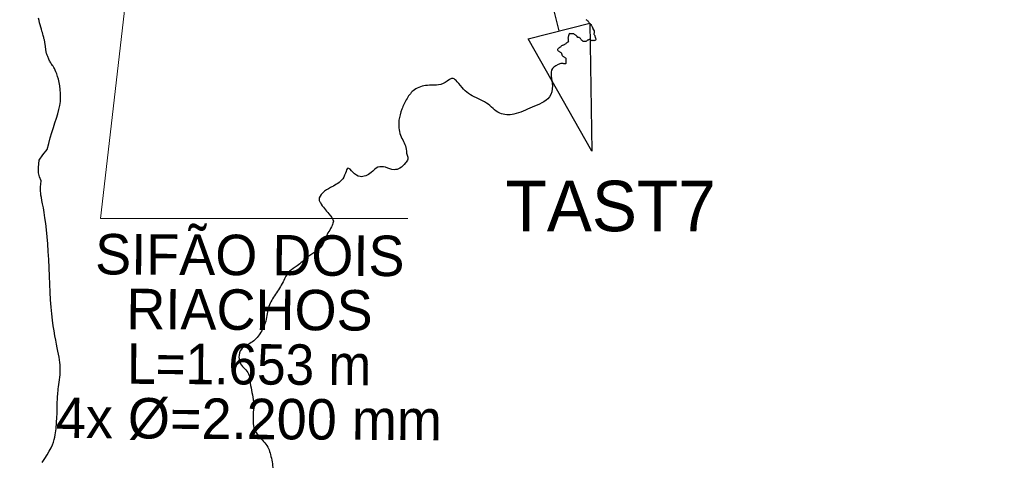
# Model space of a CAD drawing. Extents: x -1643653 to 4543381, y 1624270 to 13878484.
# Drawn here: x 707705 to 717468, y 8950266 to 8954621 of the extents above; entities that cross this region are included whole.
import ezdxf
from ezdxf.enums import TextEntityAlignment as Align

# ---------------------------------------------------------------- set-up
doc = ezdxf.new("R2010")
doc.units = 0
doc.header["$LTSCALE"] = 160
for name, color, linetype, lineweight in [('24', 7, 'Continuous', 25), ('50', 7, 'Continuous', 13), ('54', 7, 'Continuous', 25), ('60', 7, 'Continuous', 13)]:
    doc.layers.add(name, color=color, linetype=linetype, lineweight=lineweight)

msp = doc.modelspace()

# ---------------------------------------------------------------- linework, layer by layer
at = {"layer": '24'}
for points in [[(707956, 8954384.1), (707954.9, 8954391.2), (707953.6, 8954398.5), (707952.2, 8954405.9), (707950.7, 8954413.4), (707949.1, 8954421), (707947.3, 8954428.8), (707945.3, 8954437.1), (707943, 8954446), (707940.4, 8954455.9), (707937.4, 8954466.9), (707933.9, 8954479.4), (707929.9, 8954493.6), (707925.3, 8954509.7), (707920.2, 8954528), (707914.5, 8954548.1), (707908.6, 8954569.4), (707902.5, 8954591.7), (707896.6, 8954614.5), (707890.9, 8954637.2)], [(713307, 8954625.1), (713312.2, 8954621.1), (713317.1, 8954618.2), (713321.9, 8954614.9), (713325.6, 8954610), (713329.4, 8954605.2), (713333.2, 8954600.5), (713336.7, 8954595.9), (713341.3, 8954591.5), (713344.4, 8954587), (713349, 8954582.3), (713353.6, 8954578.9), (713358.5, 8954573.9), (713360.9, 8954569), (713363.1, 8954563.9), (713365.8, 8954556.9), (713369.7, 8954551.6), (713372.7, 8954547.2), (713374.2, 8954542.2), (713375.5, 8954537.1), (713376.9, 8954531.6), (713390.6, 8954512.4)], [(713229.2, 8954445.5), (713220.4, 8954455.7), (713214.5, 8954461.2), (713210.9, 8954465.8), (713206.4, 8954468.9), (713201.3, 8954471.5), (713195.4, 8954474.7), (713191.7, 8954478.3), (713187.4, 8954482.7), (713180.8, 8954482.6), (713175.8, 8954481.5), (713170.8, 8954480.4), (713165.2, 8954480.4), (713159.8, 8954482.2), (713154.6, 8954483), (713147.7, 8954483.7), (713141.9, 8954481.6), (713138.1, 8954470.5), (713137.2, 8954462.9), (713136.5, 8954457.3), (713133.9, 8954451.5), (713131.7, 8954446.4), (713130.2, 8954441), (713130.9, 8954436), (713131.5, 8954430.1), (713132.8, 8954422.3), (713133.5, 8954416.6), (713134.1, 8954410.6), (713133.8, 8954405.6), (713131.6, 8954401.1), (713127.6, 8954398), (713122.8, 8954395.4), (713118.2, 8954392.8), (713113.5, 8954388.2), (713109.7, 8954384.6), (713103.8, 8954381), (713097.1, 8954377.7), (713091.9, 8954374.4), (713085.8, 8954371.3), (713080.7, 8954368.8), (713074.7, 8954366.9), (713067.9, 8954362.2), (713063.7, 8954358.6), (713059.7, 8954355.1), (713055.1, 8954351.5), (713048.2, 8954347.9), (713042.8, 8954344.3), (713038.6, 8954340.4), (713035, 8954335.6), (713030.7, 8954331.8), (713028, 8954327.5), (713027.8, 8954322.3), (713029.7, 8954317.1), (713033.4, 8954312.2), (713038.7, 8954309.1), (713043.6, 8954307.2), (713048.9, 8954304.3), (713054.5, 8954301.2), (713059, 8954298), (713062.8, 8954294.3), (713065.3, 8954289.8), (713066.8, 8954284.8), (713069.4, 8954280.2), (713070.9, 8954274.6), (713073.7, 8954269.2)], [(713390.6, 8954512.4), (713390.3, 8954505.2), (713389.8, 8954499.3), (713389.5, 8954493.5), (713387.8, 8954479.9), (713389.8, 8954474.5), (713392.8, 8954469.2), (713395.3, 8954464.4), (713396.6, 8954457.8), (713398.5, 8954452.9), (713401.1, 8954447.1), (713402.7, 8954442.3), (713404.4, 8954437.5), (713405.7, 8954431.2), (713405.7, 8954426), (713404.1, 8954420.3), (713398.7, 8954415.7), (713392.6, 8954414.4), (713387, 8954414.2), (713381.8, 8954415.9), (713374.3, 8954414.9), (713367.8, 8954414.2), (713362.5, 8954416.7), (713357.9, 8954419.2), (713352.6, 8954422.4), (713345.1, 8954425), (713339.8, 8954424.3), (713335.1, 8954422.7), (713329, 8954420.7), (713324.1, 8954419.2), (713319.3, 8954416), (713313.1, 8954410.9), (713307.6, 8954407.2), (713300.2, 8954406.6), (713294, 8954405.8), (713288.1, 8954405.2), (713280.9, 8954407.3), (713276.2, 8954409.8), (713271, 8954414.4), (713265.9, 8954419.2), (713261.2, 8954424.5), (713258.1, 8954429), (713253.9, 8954434.3), (713250, 8954438.7), (713245.6, 8954442.5), (713240.2, 8954444.2), (713229.2, 8954445.5)], [(708079.3, 8954060.8), (708071.1, 8954085.7), (708063.2, 8954106.6), (708055.7, 8954124), (708048.6, 8954138.5), (708041.7, 8954150.6), (708035.2, 8954160.9), (708029.1, 8954169.9), (708023.1, 8954178.3), (708017.4, 8954186.5), (708012, 8954195), (708006.8, 8954203.9), (708001.8, 8954213), (707997.2, 8954222.1), (707992.8, 8954231.2), (707988.8, 8954240.2), (707985.1, 8954248.9), (707981.7, 8954257.1), (707978.7, 8954264.9), (707976, 8954272.2), (707973.6, 8954279.2), (707971.6, 8954285.9), (707969.7, 8954292.3), (707968.1, 8954298.6), (707966.8, 8954304.8), (707965.5, 8954311), (707964.5, 8954317.3), (707963.5, 8954323.6), (707962.7, 8954330.1), (707961.9, 8954336.5), (707961.2, 8954343.1), (707960.4, 8954349.7), (707959.7, 8954356.5), (707958.9, 8954363.2), (707958, 8954370.1), (707957.1, 8954377), (707956, 8954384.1)], [(708079.3, 8954060.8), (708071.1, 8954085.7), (708063.2, 8954106.6), (708055.7, 8954124), (708048.6, 8954138.5), (708041.7, 8954150.6), (708035.2, 8954160.9), (708029.1, 8954169.9), (708023.1, 8954178.3), (708017.4, 8954186.5), (708012, 8954195), (708006.8, 8954203.9), (708001.8, 8954213), (707997.2, 8954222.1), (707992.8, 8954231.2), (707988.8, 8954240.2), (707985.1, 8954248.9), (707981.7, 8954257.1), (707978.7, 8954264.9), (707976, 8954272.2), (707973.6, 8954279.2), (707971.6, 8954285.9), (707969.7, 8954292.3), (707968.1, 8954298.6), (707966.8, 8954304.8), (707965.5, 8954311), (707964.5, 8954317.3), (707963.5, 8954323.6), (707962.7, 8954330.1), (707961.9, 8954336.5), (707961.2, 8954343.1), (707960.4, 8954349.7), (707959.7, 8954356.5), (707958.9, 8954363.2), (707958, 8954370.1), (707957.1, 8954377), (707956, 8954384.1)], [(713073.7, 8954269.2), (713076.6, 8954263.4), (713080.6, 8954259.9), (713085.1, 8954256.4), (713090, 8954254.4), (713094.5, 8954251.6), (713100.2, 8954248.5), (713104.7, 8954246.1), (713107.9, 8954241.3), (713109.3, 8954236.4), (713109.3, 8954231.3), (713109.3, 8954226), (713109.3, 8954219.8), (713109.9, 8954212.4), (713109.9, 8954205.7), (713109.9, 8954200.2), (713109.7, 8954195), (713108.7, 8954189.2), (713104.5, 8954185.5), (713099.5, 8954185.1), (713094.2, 8954185.7), (713088.9, 8954185.7), (713083.8, 8954187), (713078.7, 8954187), (713059.3, 8954187.3)], [(708105.3, 8951136), (708106, 8951160.4), (708105.7, 8951184.6), (708104.4, 8951208.7), (708102.1, 8951233.3), (708098.8, 8951258.8), (708094.7, 8951285.6), (708089.7, 8951314.1), (708083.8, 8951344.7), (708077, 8951378), (708069.6, 8951414.3), (708061.6, 8951454), (708053.2, 8951497.3), (708044.9, 8951544.7), (708036.7, 8951596.3), (708028.9, 8951652.5), (708021.8, 8951713.6), (708015.7, 8951780), (708010.6, 8951851.7), (708006.3, 8951927.7), (708002.7, 8952006.7), (707999.3, 8952087.6), (707996, 8952169.1), (707992.4, 8952249.9), (707988.2, 8952328.8), (707983.1, 8952404.7), (707977, 8952476.3), (707970, 8952543.3), (707962.4, 8952605.4), (707954.5, 8952662.4), (707946.5, 8952714.1), (707938.8, 8952760.1), (707931.6, 8952800.3), (707925.2, 8952834.3), (707919.7, 8952862.3), (707915.5, 8952885.6), (707912.4, 8952906.2), (707910.7, 8952925.7), (707910.4, 8952945.9), (707911.6, 8952968.7), (707914.4, 8952995.7), (707918.9, 8953028.8), (707901.9, 8953068.2), (707891.4, 8953109.1), (707891.4, 8953159.4), (707897.7, 8953232.7), (707934.3, 8953286.2), (707978.2, 8953339.4), (707992.2, 8953397.3), (708007.2, 8953453.2), (708022.7, 8953505.9), (708038.5, 8953555.7), (708053.9, 8953602.8), (708068.4, 8953647.8), (708081.6, 8953690.9), (708092.8, 8953732.6), (708101.7, 8953773.3), (708107.5, 8953813.5), (708110.1, 8953853.3), (708109.6, 8953892.4), (708106.6, 8953930.3), (708101.6, 8953966.7), (708095.1, 8954000.8), (708087.5, 8954032.4), (708079.3, 8954060.8)], [(708105.3, 8951136), (708106, 8951160.4), (708105.7, 8951184.6), (708104.4, 8951208.7), (708102.1, 8951233.3), (708098.8, 8951258.8), (708094.7, 8951285.6), (708089.7, 8951314.1), (708083.8, 8951344.7), (708077, 8951378), (708069.6, 8951414.3), (708061.6, 8951454), (708053.2, 8951497.3), (708044.9, 8951544.7), (708036.7, 8951596.3), (708028.9, 8951652.5), (708021.8, 8951713.6), (708015.7, 8951780), (708010.6, 8951851.7), (708006.3, 8951927.7), (708002.7, 8952006.7), (707999.3, 8952087.6), (707996, 8952169.1), (707992.4, 8952249.9), (707988.2, 8952328.8), (707983.1, 8952404.7), (707977, 8952476.3), (707970, 8952543.3), (707962.4, 8952605.4), (707954.5, 8952662.4), (707946.5, 8952714.1), (707938.8, 8952760.1), (707931.6, 8952800.3), (707925.2, 8952834.3), (707919.7, 8952862.3), (707915.5, 8952885.6), (707912.4, 8952906.2), (707910.7, 8952925.7), (707910.4, 8952945.9), (707911.6, 8952968.7), (707914.4, 8952995.7), (707918.9, 8953028.8), (707901.9, 8953068.2), (707891.4, 8953109.1), (707891.4, 8953159.4), (707897.7, 8953232.7), (707934.3, 8953286.2), (707978.2, 8953339.4), (707992.2, 8953397.3), (708007.2, 8953453.2), (708022.7, 8953505.9), (708038.5, 8953555.7), (708053.9, 8953602.8), (708068.4, 8953647.8), (708081.6, 8953690.9), (708092.8, 8953732.6), (708101.7, 8953773.3), (708107.5, 8953813.5), (708110.1, 8953853.3), (708109.6, 8953892.4), (708106.6, 8953930.3), (708101.6, 8953966.7), (708095.1, 8954000.8), (708087.5, 8954032.4), (708079.3, 8954060.8)], [(707928.3, 8950244.1), (707953.9, 8950283.2), (707977.4, 8950321.1), (707997.9, 8950356.8), (708014.7, 8950389.4), (708028.1, 8950419.1), (708038.5, 8950446.2), (708046.4, 8950471.1), (708052.2, 8950494.3), (708056.5, 8950516.3), (708059.6, 8950537.3), (708062.1, 8950557.8), (708064.2, 8950578.2), (708066.1, 8950598.2), (708067.8, 8950617.9), (708069.4, 8950636.8), (708070.7, 8950654.8), (708071.8, 8950671.8), (708072.8, 8950687.4), (708073.6, 8950701.6), (708074.2, 8950714.1), (708074.7, 8950725.1), (708075.1, 8950735), (708075.3, 8950743.8), (708075.5, 8950751.9), (708075.6, 8950759.5), (708075.7, 8950766.9), (708075.8, 8950774.2), (708075.9, 8950781.8), (708075.9, 8950789.6), (708076, 8950797.8), (708076.2, 8950806.4), (708076.3, 8950815.6), (708076.6, 8950825.3), (708076.8, 8950835.8), (708077.2, 8950846.9), (708077.7, 8950858.9), (708078.2, 8950871.8), (708079, 8950885.6), (708080, 8950900.5), (708081.2, 8950916.4), (708082.7, 8950933.6), (708084.7, 8950952), (708087, 8950971.7), (708089.7, 8950992.8), (708092.7, 8951015.1), (708095.8, 8951038.3), (708098.8, 8951062.2), (708101.5, 8951086.6), (708103.8, 8951111.3), (708105.3, 8951136)]]:
    msp.add_lwpolyline(points, dxfattribs=at)
for points in [[(713059.3, 8954187.3), (712976.6, 8954138.8), (712976.6, 8953968.3), (712946.6, 8953858), (712776.2, 8953757.7), (712595.7, 8953687.5), (712455.4, 8953697.6), (712325.1, 8953797.8), (712164.7, 8953878.1), (712034.4, 8954008.5), (711995.3, 8954040.5), (711915.1, 8954000.4), (711738.7, 8953972.3), (711610.4, 8953928.2), (711538.3, 8953844), (711486.1, 8953735.7), (711458.1, 8953627.4), (711474.1, 8953478.9), (711526.2, 8953358.6), (711538.3, 8953282.4), (711546.3, 8953242.3), (711522.2, 8953206.2), (711466.1, 8953154), (711410, 8953138), (711325.8, 8953162.1), (711249.6, 8953162.1), (711181.4, 8953109.9), (711073.2, 8953069.8), (711001, 8953113.9), (710952.9, 8953154), (710928.8, 8953105.9), (710888.7, 8953033.7), (710780.5, 8952961.5), (710704.3, 8952909.3), (710668.2, 8952841.1), (710680.2, 8952813.1), (710764.5, 8952700.7)], [(710764.5, 8952700.7), (710808.6, 8952628.5), (710796.5, 8952588.4), (710732.4, 8952468.1), (710692.3, 8952383.8), (710547.9, 8952271.5), (710451.7, 8952187.3), (710375.5, 8952135.1), (710311.4, 8952030.8), (710235.2, 8951906.5), (710171.1, 8951786.1), (710139, 8951641.7), (710082.8, 8951517.4), (709994.7, 8951429.1), (709898.4, 8951365), (709874.4, 8951284.7), (709890.4, 8951220.5), (709970.6, 8951120.3), (709986.6, 8951028), (710018.7, 8950843.5), (710034.7, 8950558.7), (710082.8, 8950490.5), (710167.1, 8950382.2), (710187.1, 8950322), (710211.2, 8950177.6), (710203.1, 8950033.2), (710167.1, 8949864.7), (710094.9, 8949579.9), (710070.8, 8949411.4), (710042.8, 8949159.9), (710046.8, 8949099.7), (710030.7, 8948999.5), (709990.6, 8948903.2), (709934.5, 8948786.9), (709890.4, 8948690.6), (709890.4, 8948590.3), (709902.4, 8948498), (709846.3, 8948445.9), (709766.1, 8948413.8), (709685.9, 8948365.7), (709641.8, 8948313.5), (709629.8, 8948249.3), (709609.8, 8948080.9), (709577.7, 8947960.5), (709549.6, 8947820.1), (709525.6, 8947643.6), (709489.5, 8947483.2), (709449.4, 8947406.9), (709417.3, 8947330.7), (709393.2, 8947226.4), (709385.2, 8947106.1), (709357.2, 8947049.9), (709293, 8946997.8), (709236.9, 8946957.7), (709176.7, 8946925.6)]]:
    msp.add_spline(points, degree=3, dxfattribs=at)
at = {"layer": '50'}
msp.add_lwpolyline([(709095.1, 8957770.5), (708503.9, 8952655.6), (711546.8, 8952655.6)], dxfattribs=at)
at = {"layer": '54'}
msp.add_line((712737.1, 8955703.7), (713041.2, 8954510.7), dxfattribs=at)
msp.add_lwpolyline([(713347.1, 8954588.7), (713366.8, 8953323.3), (712735.2, 8954432.8)], close=True, dxfattribs=at)
at = {"layer": '60', "lineweight": 25}
msp.add_spline([(814781, 9009175.5), (814787.2, 9009173.4), (814796.9, 9009173.4), (814799.4, 9009172.4), (814805.1, 9009174.5), (814805.6, 9009176.5), (814811.7, 9009179.5), (814811.7, 9009179.5), (814801.5, 9009181), (814790.7, 9009181.5), (814784.1, 9009183.1), (814777.4, 9009185.1), (814778.4, 9009175.5)], degree=3, dxfattribs=at)

# ---------------------------------------------------------------- texts
at = {"layer": '50'}
for s, p in [('SIFÃO DOIS', (709981, 8952095)), ('RIACHOS', (709977.8, 8951555)), ('4x Ø=2.200 mm', (709971.3, 8950475.1))]:
    msp.add_text(s, height=400, rotation=359.655, dxfattribs=at).set_placement(p, align=Align.CENTER)
at = {"layer": '50', "width": 0.95}
msp.add_text('L=1.653 m', height=400, rotation=359.655, dxfattribs=at).set_placement((709974.5, 8951015.1), align=Align.CENTER)
at = {"layer": '54'}
msp.add_text('TAST7', height=500, dxfattribs=at).set_placement((713553.1, 8952529.8), align=Align.CENTER)

doc.saveas('drawing.dxf')
